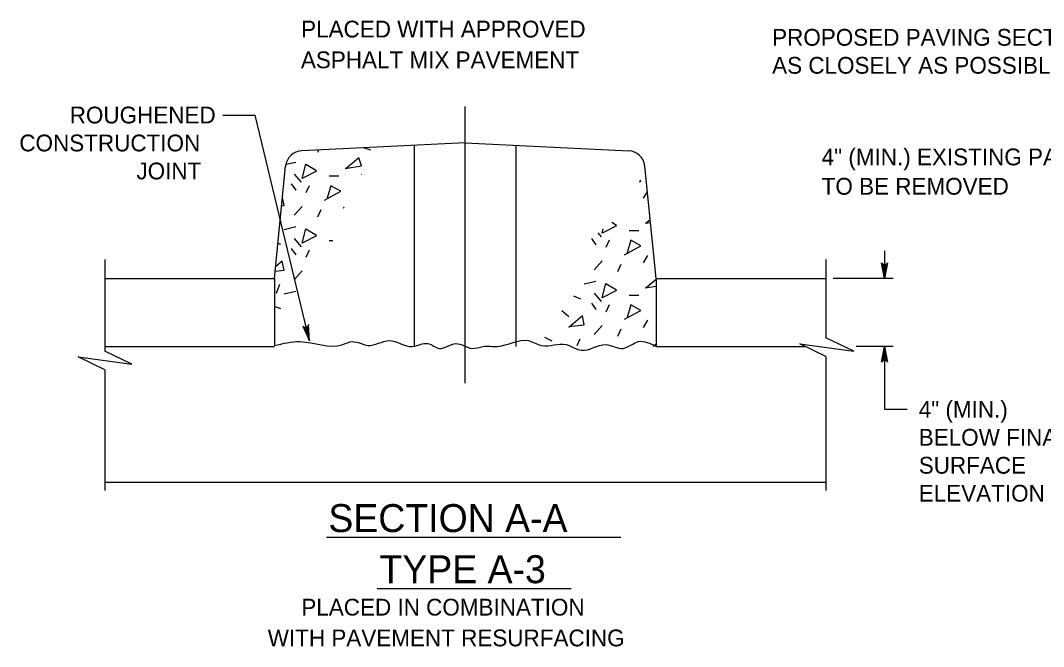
# Model space of a CAD drawing. Extents: x -49.1 to -41.9, y 44.5 to 54.6.
# Drawn here: x -48.919 to -45.264, y 50.157 to 52.396 of the extents above; entities that cross this region are included whole.
import ezdxf

# ---------------------------------------------------------------- set-up
doc = ezdxf.new("R2010")
doc.units = 0
for name, color, linetype in [('DETL-DIMS', 7, 'Continuous'), ('DETL-LINE', 7, 'Continuous'), ('DETL-NOTE', 7, 'Continuous'), ('DETL-PATT', 7, 'Continuous'), ('DETL-TITL', 7, 'Continuous')]:
    doc.layers.add(name, color=color, linetype=linetype)

msp = doc.modelspace()

# ---------------------------------------------------------------- linework, layer by layer
at = {"layer": 'DETL-DIMS'}
for p, q in [((-47.3302, 51.0992), (-47.3302, 52.088)), ((-48.1967, 52.0577), (-48.081, 52.0577)), ((-47.8869, 51.2508), (-48.081, 52.0577)), ((-45.832, 51.5725), (-45.832, 51.4728)), ((-45.8013, 51.4728), (-46.0154, 51.4728)), ((-45.8013, 51.2304), (-45.9336, 51.2304)), ((-45.832, 51.2304), (-45.832, 51.0055)), ((-45.832, 51.0055), (-45.7515, 51.0055))]:
    msp.add_line(p, q, dxfattribs=at)
for points in [[(-45.832, 51.4728), (-45.8425, 51.5293), (-45.8395, 51.525), (-45.8358, 51.5227), (-45.832, 51.5221), (-45.8282, 51.5227), (-45.8244, 51.525), (-45.8214, 51.5293), (-45.832, 51.4728), (-45.8244, 51.525), (-45.8282, 51.5227), (-45.832, 51.4728), (-45.832, 51.5221), (-45.8358, 51.5227), (-45.832, 51.4728), (-45.8395, 51.525)], [(-47.8869, 51.2508), (-47.8898, 51.3082), (-47.8917, 51.3033), (-47.8948, 51.3002), (-47.8984, 51.2987), (-47.9022, 51.2984), (-47.9064, 51.2997), (-47.9104, 51.3033), (-47.8869, 51.2508), (-47.9064, 51.2997), (-47.9022, 51.2984), (-47.8869, 51.2508), (-47.8984, 51.2987), (-47.8948, 51.3002), (-47.8869, 51.2508), (-47.8917, 51.3033)], [(-45.832, 51.2304), (-45.8214, 51.1739), (-45.8244, 51.1783), (-45.8282, 51.1805), (-45.832, 51.1811), (-45.8358, 51.1805), (-45.8395, 51.1783), (-45.8425, 51.1739), (-45.832, 51.2304), (-45.8395, 51.1783), (-45.8358, 51.1805), (-45.832, 51.2304), (-45.832, 51.1811), (-45.8282, 51.1805), (-45.832, 51.2304), (-45.8244, 51.1783)]]:
    msp.add_lwpolyline(points, dxfattribs=at)
at = {"layer": 'DETL-LINE'}
for p, q in [((-47.3302, 51.9577), (-47.9142, 51.9299)), ((-47.512, 51.2304), (-47.512, 51.949)), ((-47.3302, 51.9577), (-46.7461, 51.9299)), ((-47.1484, 51.2304), (-47.1484, 51.949)), ((-48.0119, 51.4728), (-47.9717, 51.8754)), ((-46.6485, 51.4728), (-46.6887, 51.8754)), ((-48.618, 51.5411), (-48.618, 51.2135)), ((-46.0424, 51.5411), (-46.0424, 51.2607)), ((-48.618, 51.4728), (-48.0119, 51.4728)), ((-48.0119, 51.4728), (-48.0119, 51.2334)), ((-46.6485, 51.4728), (-46.0424, 51.4728)), ((-46.6485, 51.4728), (-46.6485, 51.2304)), ((-48.618, 51.2304), (-48.0119, 51.2304)), ((-46.6485, 51.2304), (-46.1165, 51.2304)), ((-46.0424, 51.1941), (-46.0424, 50.7156)), ((-48.618, 51.1469), (-48.618, 50.7156)), ((-48.618, 50.7455), (-46.0424, 50.7455))]:
    msp.add_line(p, q, dxfattribs=at)
for points in [[(-46.0424, 51.1941), (-46.1343, 51.2391), (-45.9421, 51.213), (-46.0424, 51.2607)], [(-48.618, 51.1469), (-48.7131, 51.1935), (-48.5209, 51.1673), (-48.618, 51.2135)]]:
    msp.add_lwpolyline(points, dxfattribs=at)
for centre, start, end in [((-47.9114, 51.8693), 92.7268, 174.2895), ((-46.749, 51.8693), 5.7105, 87.2732)]:
    msp.add_arc(centre, 0.0606, start, end, dxfattribs=at)
msp.add_spline([(-48.0119, 51.2334), (-47.9198, 51.2476), (-47.7678, 51.2372), (-47.7333, 51.2476), (-47.678, 51.2338), (-47.602, 51.251), (-47.5191, 51.2303), (-47.4639, 51.2407), (-47.4224, 51.2234), (-47.3637, 51.2407), (-47.305, 51.2234), (-47.267, 51.2303), (-47.2152, 51.2303), (-47.1047, 51.251), (-47.0563, 51.2338), (-46.97, 51.2372), (-46.9147, 51.2165), (-46.8284, 51.2372), (-46.7662, 51.2234), (-46.711, 51.2476), (-46.6485, 51.2304)], degree=3, dxfattribs=at)
at = {"layer": 'DETL-PATT'}
for p, q in [((-47.6915, 51.9398), (-47.6691, 51.9334)), ((-47.8538, 51.933), (-47.8584, 51.9237)), ((-47.9354, 51.8885), (-47.9705, 51.8804)), ((-47.9419, 51.8467), (-47.9162, 51.8179)), ((-47.8167, 51.8403), (-47.7814, 51.8403)), ((-47.7012, 51.8467), (-47.6991, 51.8449)), ((-47.9515, 51.8114), (-47.9354, 51.789)), ((-47.8873, 51.805), (-47.9001, 51.7794)), ((-46.6935, 51.7606), (-46.6795, 51.783)), ((-47.913, 51.7312), (-47.9419, 51.6991)), ((-47.7654, 51.7248), (-47.7623, 51.7296)), ((-47.8456, 51.7184), (-47.8584, 51.6927)), ((-47.9354, 51.6574), (-47.9771, 51.6478)), ((-47.9419, 51.6157), (-47.9162, 51.5868)), ((-46.8796, 51.6161), (-46.8636, 51.5937)), ((-46.8563, 51.636), (-46.8443, 51.6226)), ((-46.8154, 51.6097), (-46.8283, 51.5841)), ((-46.7448, 51.645), (-46.7095, 51.645)), ((-47.9992, 51.5999), (-47.99, 51.5964)), ((-47.9515, 51.5804), (-47.9354, 51.5579)), ((-47.8873, 51.574), (-47.9001, 51.5483)), ((-47.8167, 51.6092), (-47.8026, 51.6092)), ((-46.6935, 51.5295), (-46.6774, 51.5552)), ((-47.913, 51.5001), (-47.9419, 51.4681)), ((-46.8411, 51.5359), (-46.87, 51.5038)), ((-46.7737, 51.5231), (-46.7866, 51.4974)), ((-47.9932, 51.452), (-48.006, 51.4199)), ((-46.8636, 51.4621), (-46.9053, 51.4525)), ((-47.9354, 51.4263), (-47.9771, 51.4167)), ((-46.9438, 51.4108), (-46.9181, 51.4011)), ((-46.87, 51.4204), (-46.8443, 51.3915)), ((-46.7448, 51.414), (-46.7095, 51.414)), ((-48.0133, 51.3741), (-47.99, 51.3654)), ((-46.9855, 51.3594), (-46.9599, 51.337)), ((-46.8796, 51.3851), (-46.8636, 51.3626)), ((-46.8154, 51.3787), (-46.8283, 51.353)), ((-46.6935, 51.2984), (-46.6774, 51.3241)), ((-46.8411, 51.3049), (-46.87, 51.2728)), ((-46.7737, 51.292), (-46.7866, 51.2664)), ((-47.0465, 51.2631), (-47.0208, 51.2503)), ((-46.9213, 51.2567), (-46.931, 51.2325))]:
    msp.add_line(p, q, dxfattribs=at)
for points in [[(-47.7589, 51.866), (-47.7012, 51.8756), (-47.7108, 51.9045), (-47.7557, 51.866)], [(-47.8616, 51.8564), (-47.913, 51.8307), (-47.9001, 51.882), (-47.8616, 51.8596)], [(-47.8327, 51.7537), (-47.775, 51.7858), (-47.8103, 51.805), (-47.8231, 51.7601)], [(-46.7073, 51.8192), (-46.7031, 51.8215), (-46.706, 51.8231)], [(-47.9859, 51.7334), (-47.9771, 51.7344), (-47.9829, 51.7631)], [(-46.6695, 51.683), (-46.6839, 51.6707)], [(-47.8616, 51.6253), (-47.913, 51.5996), (-47.9001, 51.651), (-47.8616, 51.6285)], [(-46.7898, 51.6611), (-46.8411, 51.6354), (-46.8373, 51.6505)], [(-46.8065, 51.6741), (-46.7898, 51.6643)], [(-46.6871, 51.6707), (-46.6686, 51.6738)], [(-46.7609, 51.5584), (-46.7031, 51.5905), (-46.7384, 51.6097), (-46.7512, 51.5648)], [(-48.0093, 51.4996), (-47.9771, 51.5034), (-47.9836, 51.5355), (-48.0078, 51.5145)], [(-46.6485, 51.47), (-46.6839, 51.4396)], [(-46.7898, 51.43), (-46.8411, 51.4044), (-46.8283, 51.4557), (-46.7898, 51.4332)], [(-46.6871, 51.4396), (-46.6485, 51.4461)], [(-46.7609, 51.3273), (-46.7031, 51.3594), (-46.7384, 51.3787), (-46.7512, 51.3337)], [(-46.9599, 51.3016), (-46.9053, 51.3081), (-46.9117, 51.3402), (-46.9599, 51.2984)], [(-46.6485, 51.2389), (-46.6583, 51.2305)]]:
    msp.add_lwpolyline(points, dxfattribs=at)
at = {"layer": 'DETL-TITL'}
for p, q in [((-47.8254, 50.548), (-46.7748, 50.548)), ((-47.6448, 50.3653), (-46.9517, 50.3653))]:
    msp.add_line(p, q, dxfattribs=at)

# ---------------------------------------------------------------- texts
at = {"layer": 'DETL-NOTE'}
for s, p in [('PLACED WITH APPROVED', (-47.9165, 52.3349)), ('PROPOSED PAVING SECTION', (-46.2337, 52.3054)), ('ASPHALT MIX PAVEMENT', (-47.9173, 52.2249)), ('AS CLOSELY AS POSSIBLE', (-46.2337, 52.2054)), ('ROUGHENED', (-48.7432, 52.0277)), ('CONSTRUCTION', (-48.9232, 51.9277)), ('4" (MIN.) EXISTING PAV\'T.', (-46.0568, 51.8779)), ('JOINT', (-48.5048, 51.8277)), ('TO BE REMOVED', (-46.0568, 51.7729)), ('4" (MIN.)', (-45.7099, 50.9755)), ('BELOW FINAL', (-45.7099, 50.8755)), ('SURFACE', (-45.7099, 50.7755)), ('ELEVATION', (-45.7099, 50.6755)), ('PLACED IN COMBINATION', (-47.9157, 50.2682)), ('WITH PAVEMENT RESURFACING', (-48.0357, 50.1582))]:
    msp.add_text(s, height=0.06, dxfattribs=at).set_placement(p)
at = {"layer": 'DETL-TITL'}
for s, p in [('SECTION A-A', (-47.8191, 50.5666)), ('TYPE A-3', (-47.6367, 50.3839))]:
    msp.add_text(s, height=0.1, dxfattribs=at).set_placement(p)

doc.saveas('drawing.dxf')
